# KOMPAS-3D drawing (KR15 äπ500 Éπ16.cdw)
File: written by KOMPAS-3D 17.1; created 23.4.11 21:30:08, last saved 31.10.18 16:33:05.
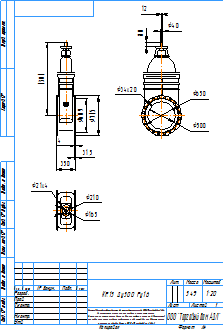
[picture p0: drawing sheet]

Sheet 1: A4, portrait

Title block, sheet 1: name: KR15 Ду500 Ру16; mass: 549; sheets: 1; sheet format: A4; stored path: \\adlc.lan\data\АДЛ_ПКД\3D-модели\ADL production\Клиновые задвижки серии KR ГРАНАР\Клиновые задвижки KR15\С голым штоком\KOMPAS 2D\KR15 Ду500 Ру16.cdw

Views: Спереди 4, Проекционный вид 5, Проекционный вид 6
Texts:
  Рама для чертежей
  Лит-Масса-Масштаб
  Материал-Предприятие
  Масштаб
  Изм.
  Лист
  № докум.
  Подп.
  Дата
  Лит.
  Разраб.
  Пров.
  Т.контр.
  Листов
  Внимание! Данный продукт является объектом авторского права ООО «Торговый Дом АДЛ».
  Запрещается изменение, копирование, распространение
  (в том числе путем копирования на другие сайты и ресурсы в Интернете)
  или любое иное использование информации и объектов без предварительного
  согласия правообладателя (ООО «Торговый Дом АДЛ»).
  Н.контр.
  Утв.
  ООО "Торговый дом АДЛ"
  Изменение
  Номер документа
  Подпись
  Обозначение документа
  Наименование изделия
  Масса изделия по ГОСТ 2.109-73
  Порядковый номер листа
  Общее количество листов в документе
  Характер работы, выполненной лицом, подписавшим документ
  Наименование или индекс предприятия, выпускающего документ
  Инв. № подл.
  Подп. и дата
  Взам. инв. №
  Инв. № дубл.
  Инвентарный номер подлинника по ГОСТ 2.501-68
  Подпись принявшего подлинник в отдел технической документации
  Инвентарный номер подлинника, взамен которого выпущен данный подлинник
  Инвентарный номер дубликата по ГОСТ 2.502-68
  Подпись принявшего дубликат в отдел технической документации
  Справ. №
  Перв. примен.
  Обозначение документа, взамен или на основании которого выпущен данный документ
  Обозначение документа, в котором впервые записан данный документ
  Подпись лица, копировавшего чертеж
  Обозначение формата листа
  !Рама для чертежа
Dimensions and other numbers on the sheet: 350; 609; 715; 1301; 4; 31,5; 210; 21; 165; 12; 80; 650; 500; 34; 40; 1:20; 1; 549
